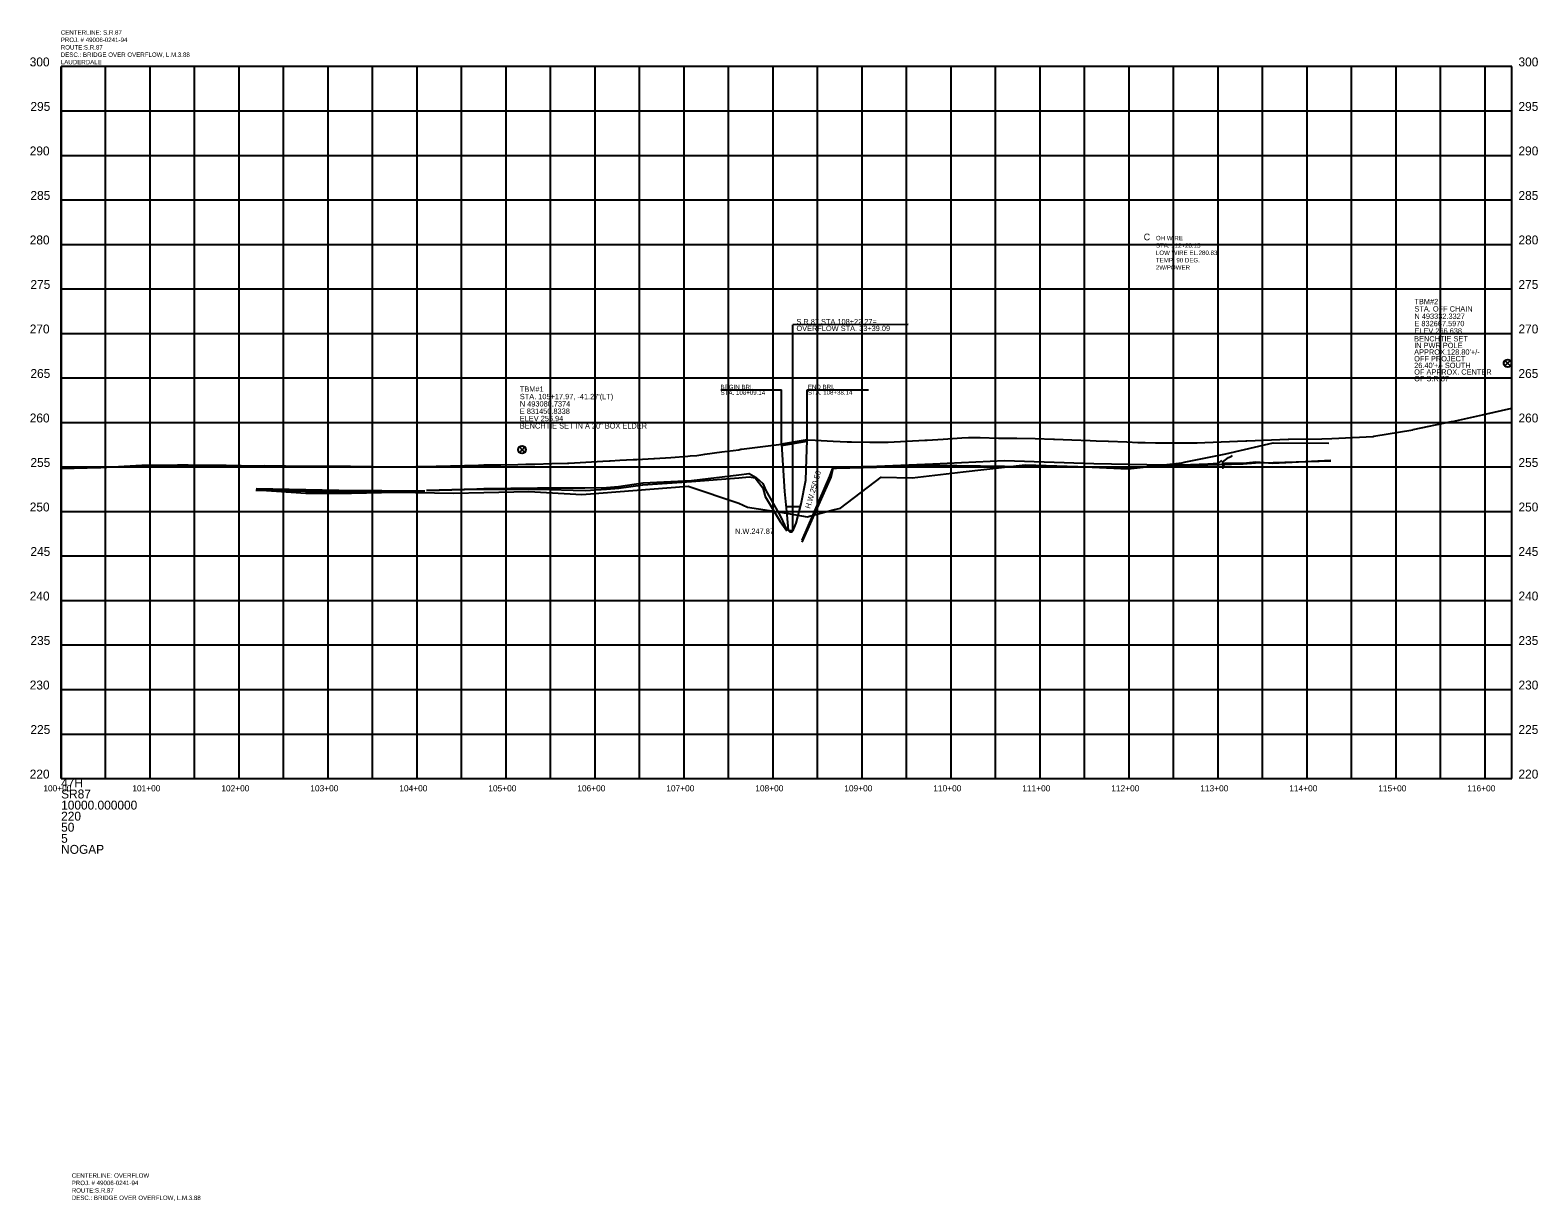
# Model space of a CAD drawing. Extents: x 818717 to 846077, y 440014 to 541392.
# Drawn here: x 836438 to 838132, y 493086 to 494401 of the extents above; entities that cross this region are included whole.
import ezdxf

# ---------------------------------------------------------------- set-up
doc = ezdxf.new("R2010")
doc.units = 0
for name, color, linetype in [('DESIGN - SHEET - Corner Text', 7, 'Continuous'), ('DESIGN - SHEET - Light Grid', 7, 'Continuous'), ('SURVEY - DRAINAGE - Bridge Hydraulic Data with Text', 7, 'Continuous'), ('SURVEY - PROFILE - Control with Text', 7, 'Continuous'), ('SURVEY - PROFILE - Drainage - Bridges', 7, 'Continuous'), ('SURVEY - PROFILE - Drainage - Bridges Text', 7, 'Continuous'), ('SURVEY - PROFILE - Drainage - Natural Features with Text', 7, 'Continuous'), ('SURVEY - PROFILE - Ground Line with Text', 7, 'Continuous'), ('SURVEY - PROFILE - Project Information and Notes', 7, 'Continuous'), ('SURVEY - PROFILE - Utilities - Overhead Wire Crossings', 7, 'Continuous'), ('SURVEY - PROFILE - Utilities - Telephone with Text', 7, 'Continuous'), ('SURVEY - PROFILE - Utilities - Water with Text', 7, 'Continuous')]:
    doc.layers.add(name, color=color, linetype=linetype)

msp = doc.modelspace()

# ---------------------------------------------------------------- linework, layer by layer
at = {"layer": 'DESIGN - SHEET - Light Grid'}
for p, q in [((838103.1, 494360.6), (836473.1, 494360.6)), ((836473.1, 494360.6), (836473.1, 493560.6)), ((836473.1, 493560.6), (836473.1, 494360.6)), ((836523.1, 493560.6), (836523.1, 494360.6)), ((836573.1, 493560.6), (836573.1, 494360.6)), ((836623.1, 493560.6), (836623.1, 494360.6)), ((836673.1, 493560.6), (836673.1, 494360.6)), ((836723.1, 493560.6), (836723.1, 494360.6)), ((836773.1, 493560.6), (836773.1, 494360.6)), ((836823.1, 493560.6), (836823.1, 494360.6)), ((836873.1, 493560.6), (836873.1, 494360.6)), ((836923.1, 493560.6), (836923.1, 494360.6)), ((836973.1, 493560.6), (836973.1, 494360.6)), ((837023.1, 493560.6), (837023.1, 494360.6)), ((837073.1, 493560.6), (837073.1, 494360.6)), ((837123.1, 493560.6), (837123.1, 494360.6)), ((837173.1, 493560.6), (837173.1, 494360.6)), ((837223.1, 493560.6), (837223.1, 494360.6)), ((837273.1, 493560.6), (837273.1, 494360.6)), ((837323.1, 493560.6), (837323.1, 494360.6)), ((837373.1, 493560.6), (837373.1, 494360.6)), ((837423.1, 493560.6), (837423.1, 494360.6)), ((837473.1, 493560.6), (837473.1, 494360.6)), ((837523.1, 493560.6), (837523.1, 494360.6)), ((837573.1, 493560.6), (837573.1, 494360.6)), ((837623.1, 493560.6), (837623.1, 494360.6)), ((837673.1, 493560.6), (837673.1, 494360.6)), ((837723.1, 493560.6), (837723.1, 494360.6)), ((837773.1, 493560.6), (837773.1, 494360.6)), ((837823.1, 493560.6), (837823.1, 494360.6)), ((837873.1, 493560.6), (837873.1, 494360.6)), ((837923.1, 493560.6), (837923.1, 494360.6)), ((837973.1, 493560.6), (837973.1, 494360.6)), ((838023.1, 493560.6), (838023.1, 494360.6)), ((838073.1, 493560.6), (838073.1, 494360.6)), ((838103.1, 493560.6), (838103.1, 494360.6)), ((836473.1, 494310.6), (838103.1, 494310.6)), ((836473.1, 494260.6), (838103.1, 494260.6)), ((836473.1, 494210.6), (838103.1, 494210.6)), ((836473.1, 494160.6), (838103.1, 494160.6)), ((836473.1, 494110.6), (838103.1, 494110.6)), ((836473.1, 494060.6), (838103.1, 494060.6)), ((836473.1, 494010.6), (838103.1, 494010.6)), ((836473.1, 493960.6), (838103.1, 493960.6)), ((836473.1, 493910.6), (838103.1, 493910.6)), ((836473.1, 493860.6), (838103.1, 493860.6)), ((836473.1, 493810.6), (838103.1, 493810.6)), ((836473.1, 493760.6), (838103.1, 493760.6)), ((836473.1, 493710.6), (838103.1, 493710.6)), ((836473.1, 493660.6), (838103.1, 493660.6)), ((836473.1, 493610.6), (838103.1, 493610.6)), ((836473.1, 493560.6), (838103.1, 493560.6)), ((836473.1, 493560.6), (838103.1, 493560.6)), ((836473.1, 493560.6), (836473.1, 493560.6))]:
    msp.add_line(p, q, dxfattribs=at)
at = {"layer": 'SURVEY - DRAINAGE - Bridge Hydraulic Data with Text'}
for p, q in [((837287.6, 493866.2), (837303.1, 493866.2)), ((837290.7, 493839.3), (837295, 493839.3))]:
    msp.add_line(p, q, dxfattribs=at)
at = {"layer": 'SURVEY - PROFILE - Control with Text'}
for p, q in [((838095.4, 494030.2), (838098.4, 494027.1)), ((838098.4, 494027.1), (838101.5, 494030.2)), ((838095.4, 494024.1), (838098.4, 494027.1)), ((838098.4, 494027.1), (838101.5, 494024.1)), ((836988, 493933.1), (836991, 493930)), ((836988, 493926.9), (836991, 493930)), ((836991, 493930), (836994.1, 493933.1)), ((836991, 493930), (836994.1, 493926.9))]:
    msp.add_line(p, q, dxfattribs=at)
for points in [[(838095.4, 494030.2), (838098.4, 494027.1), (838095.4, 494024.1), (838095.1, 494024.3), (838094.9, 494024.7), (838094.7, 494024.9), (838094.6, 494025.2), (838094.4, 494025.5), (838094.3, 494025.8), (838094.2, 494026.1), (838094.2, 494026.4), (838094.1, 494026.7), (838094.1, 494026.9), (838094.1, 494027.3), (838094.1, 494027.5), (838094.2, 494027.8), (838094.2, 494028), (838094.2, 494028.2), (838094.3, 494028.5), (838094.4, 494028.7), (838094.5, 494028.9), (838094.7, 494029.3), (838094.9, 494029.6), (838095.1, 494029.9)], [(838101.5, 494030.2), (838098.4, 494027.1), (838101.5, 494024.1), (838101.7, 494024.3), (838101.9, 494024.5), (838102.2, 494024.9), (838102.3, 494025.1), (838102.5, 494025.5), (838102.6, 494025.8), (838102.7, 494026.1), (838102.7, 494026.3), (838102.8, 494026.7), (838102.8, 494026.9), (838102.8, 494027.2), (838102.8, 494027.5), (838102.8, 494027.7), (838102.7, 494028), (838102.7, 494028.2), (838102.6, 494028.5), (838102.5, 494028.8), (838102.4, 494029), (838102.3, 494029.2), (838102, 494029.6), (838101.8, 494029.9)], [(836988, 493933.1), (836991, 493930), (836988, 493926.9), (836987.7, 493927.2), (836987.5, 493927.5), (836987.3, 493927.8), (836987.1, 493928.1), (836987, 493928.4), (836986.9, 493928.7), (836986.8, 493928.9), (836986.8, 493929.2), (836986.7, 493929.5), (836986.7, 493929.8), (836986.7, 493930.1), (836986.7, 493930.4), (836986.7, 493930.6), (836986.8, 493930.8), (836986.8, 493931), (836986.9, 493931.3), (836987, 493931.5), (836987.1, 493931.8), (836987.2, 493932.1), (836987.4, 493932.4), (836987.7, 493932.8)], [(836994.1, 493933.1), (836991, 493930), (836994.1, 493926.9), (836994.3, 493927.1), (836994.5, 493927.4), (836994.7, 493927.7), (836994.9, 493928), (836995.1, 493928.4), (836995.2, 493928.7), (836995.3, 493929), (836995.3, 493929.2), (836995.4, 493929.5), (836995.4, 493929.8), (836995.4, 493930.1), (836995.4, 493930.4), (836995.3, 493930.6), (836995.3, 493930.9), (836995.3, 493931.1), (836995.2, 493931.3), (836995, 493931.7), (836995, 493931.9), (836994.8, 493932.1), (836994.6, 493932.4), (836994.4, 493932.8)]]:
    msp.add_lwpolyline(points, close=True, dxfattribs=at)
for centre in [(838098.5, 494027.1), (836991, 493930)]:
    msp.add_circle(centre, 4.35, dxfattribs=at)
at = {"layer": 'SURVEY - PROFILE - Drainage - Bridges'}
for p, q in [((837311.2, 493941.1), (837282.5, 493936.3)), ((837311.2, 493939.2), (837282.6, 493934.5))]:
    msp.add_line(p, q, dxfattribs=at)
at = {"layer": 'SURVEY - PROFILE - Drainage - Bridges Text'}
for p, q in [((837214.2, 493997.4), (837282.5, 493997.4)), ((837311.2, 493997.4), (837380.1, 493997.4))]:
    msp.add_line(p, q, dxfattribs=at)
for points in [[(837282.5, 493936.3), (837282.5, 493997.4)], [(837311.2, 493941.1), (837311.2, 493997.4)]]:
    msp.add_lwpolyline(points, dxfattribs=at)
at = {"layer": 'SURVEY - PROFILE - Ground Line with Text'}
msp.add_line((837424.9, 494070.6), (837295.3, 494070.1), dxfattribs=at)
for points in [[(837295.3, 493839.9), (837295.3, 494070.1)], [(836473.1, 493908.8), (836473.6, 493908.8), (836516.6, 493909.9), (836517.7, 493909.9), (836563.6, 493912.5), (836564.6, 493912.6), (836603.9, 493912.8), (836616, 493912.8), (836658.4, 493912.6), (836692.2, 493912), (836701.8, 493912.3), (836702.1, 493912.3), (836748.6, 493911.4), (836749.4, 493911.4), (836797.7, 493911.5), (836798.4, 493911.5), (836847.2, 493910.7), (836847.9, 493910.7), (836848.3, 493910.7), (836894.4, 493911.5), (836895, 493911.5), (836941.9, 493912.7), (836948.2, 493912.8), (836967.3, 493913.1), (836986.4, 493913.4), (836995.1, 493913.6), (836995.7, 493913.6), (837005.5, 493913.8), (837024.6, 493914.3), (837042.1, 493914.7), (837043, 493914.7), (837043.7, 493914.8), (837062.8, 493915.9), (837081.9, 493917.1), (837089.4, 493917.6), (837089.7, 493917.6), (837090, 493917.6), (837101, 493918.2), (837115.9, 493918.9), (837120.1, 493919.1), (837139.2, 493920.1), (837139.5, 493920.1), (837139.9, 493920.1), (837158.3, 493921.4), (837177.4, 493922.8), (837179.9, 493923), (837187.3, 493923.5), (837196.5, 493924.8), (837215.6, 493927.4), (837234.7, 493930), (837237, 493930.4), (837237.5, 493930.4), (837282.5, 493936.3), (837286, 493883.2), (837288.5, 493856.9), (837290.1, 493839.5), (837291.7, 493837.7), (837294.3, 493837.7), (837296, 493840.2), (837298.9, 493847.5), (837304.6, 493869.3), (837309.9, 493895.9), (837310.6, 493919.3), (837311.2, 493940.5), (837311.2, 493941.1), (837320.2, 493940.6), (837340.6, 493939.5), (837356.3, 493938.7), (837361.2, 493938.7), (837381.8, 493938.5), (837401, 493938.4), (837401.4, 493938.4), (837402.5, 493938.5), (837423.1, 493939.5), (837443.7, 493940.6), (837445.8, 493940.8), (837446.3, 493940.8), (837464.3, 493941.9), (837485, 493943.2), (837492.5, 493943.7), (837493, 493943.7), (837493.5, 493943.7), (837505.6, 493943.5), (837526.2, 493943.1), (837540, 493942.9), (837540.9, 493942.9), (837541.5, 493942.9), (837546.8, 493942.8), (837567.4, 493942.4), (837588.3, 493941.9), (837589, 493941.9), (837589.4, 493941.9), (837608.7, 493941.1), (837629.3, 493940.4), (837636.2, 493940.1), (837649.5, 493939.6), (837649.9, 493939.6), (837670.5, 493938.7), (837683, 493938.2), (837688.7, 493938.1), (837691.2, 493938.1), (837702.9, 493937.8), (837703.3, 493937.8), (837711.8, 493937.8), (837732.4, 493937.7), (837736.2, 493937.7), (837749.6, 493937.6), (837758.3, 493938), (837804.2, 493939.9), (837804.6, 493940), (837805.2, 493940), (837852, 493941.8), (837852.5, 493941.8), (837889.6, 493942.3), (837900.7, 493942.4), (837947.4, 493944.9), (837948.2, 493945), (837991.9, 493952.4), (837992.4, 493952.5), (838035.2, 493961.6), (838036.3, 493961.8), (838070.1, 493969.1), (838071.7, 493969.4), (838103, 493976.5)]]:
    msp.add_lwpolyline(points, dxfattribs=at)
at = {"layer": 'SURVEY - PROFILE - Utilities - Telephone with Text'}
for points in [[(837305.6, 493828.4), (837337, 493900.3), (837340.6, 493910.5), (837344, 493910.5), (837389.5, 493911.4), (837452.7, 493914), (837533, 493917.7), (837633.4, 493914.4), (837693, 493913.5), (837732.4, 493913.1), (837761.4, 493912.8), (837801.2, 493914.1), (837815.3, 493915.2), (837834.8, 493915.6), (837899.7, 493917.6)], [(837305.7, 493826.2), (837338.5, 493899.1), (837340.6, 493909.1), (837344.3, 493909.1), (837389.4, 493910.3), (837452.7, 493912.5), (837533.1, 493911.4), (837634, 493910.4), (837693, 493911.1), (837732.4, 493912.9), (837761.4, 493914.2), (837773.6, 493914.7), (837777.1, 493918.4)], [(837777.9, 493916.4), (837778.4, 493909.3), (837780.8, 493914.9), (837801.2, 493914.8), (837815.6, 493916.3), (837834.7, 493914.8), (837899.6, 493918.4)], [(837778.2, 493916.1), (837784.7, 493921.3), (837787.8, 493922.4), (837789.4, 493923.4)], [(836883.8, 493884.4), (836940.3, 493886.2), (836948.2, 493886.3), (837008.5, 493887.2), (837061.7, 493887.1), (837085.9, 493887.4), (837099.3, 493888.5), (837126.9, 493892.6), (837181.4, 493895.4), (837234.7, 493901.9), (837246.2, 493903.4), (837253.9, 493898.8), (837261.4, 493892.1), (837265, 493884.3), (837281.2, 493855.7), (837288.6, 493839.7)], [(836884.1, 493884), (836940.5, 493885.5), (836948.2, 493885.5), (837008.3, 493885.5), (837061.9, 493884.1), (837085.8, 493885.6), (837099.6, 493886.9), (837126.6, 493890.5), (837181.5, 493894.1), (837234.7, 493898.5), (837246.3, 493899.5), (837253, 493898.5), (837261.5, 493887.2), (837264.1, 493877.3), (837281, 493849.3), (837288.6, 493838.7)], [(836692, 493884.7), (836784.9, 493882.7), (836881.4, 493882.5)], [(836692.2, 493886.5), (836785.1, 493884.6), (836881.6, 493883.8)]]:
    msp.add_lwpolyline(points, dxfattribs=at)
at = {"layer": 'SURVEY - PROFILE - Utilities - Water with Text'}
msp.add_lwpolyline([(836693.1, 493885), (836748.2, 493881.3), (836799.4, 493881.1), (836849.8, 493882.1), (836913.9, 493881.3), (836948.2, 493882), (836998.6, 493883.2), (837058.3, 493879.7), (837177.7, 493888.9), (837234.7, 493870), (837244.4, 493865.6), (837281.3, 493859.8), (837311.4, 493854.5), (837340.6, 493862.4), (837348.9, 493864.4), (837394.4, 493899.2), (837429.5, 493898.4), (837486.8, 493905.2), (837556.3, 493913), (837615.6, 493911.2), (837672, 493908.4), (837732.4, 493915.3), (837735.1, 493916.1), (837781.9, 493925.5), (837834.9, 493937.6), (837897.6, 493937.4)], dxfattribs=at)

# ---------------------------------------------------------------- texts
at = {"layer": 'DESIGN - SHEET - Corner Text'}
for s, height, p in [('300', 10, (836437.8, 494360.6)), ('300', 10, (838110.6, 494360.6)), ('295', 10, (836438.6, 494310.6)), ('295', 10, (838110.6, 494310.6)), ('290', 10, (836437.8, 494260.6)), ('290', 10, (838110.6, 494260.6)), ('285', 10, (836438.6, 494210.6)), ('285', 10, (838110.6, 494210.6)), ('280', 10, (836437.8, 494160.6)), ('280', 10, (838110.6, 494160.6)), ('275', 10, (836438.6, 494110.6)), ('275', 10, (838110.6, 494110.6)), ('270', 10, (836437.8, 494060.6)), ('270', 10, (838110.6, 494060.6)), ('265', 10, (836438.6, 494010.6)), ('265', 10, (838110.6, 494010.6)), ('260', 10, (836437.8, 493960.6)), ('260', 10, (838110.6, 493960.6)), ('255', 10, (836438.6, 493910.6)), ('255', 10, (838110.6, 493910.6)), ('250', 10, (836437.8, 493860.6)), ('250', 10, (838110.6, 493860.6)), ('245', 10, (836438.6, 493810.6)), ('245', 10, (838110.6, 493810.6)), ('240', 10, (836437.8, 493760.6)), ('240', 10, (838110.6, 493760.6)), ('235', 10, (836438.6, 493710.6)), ('235', 10, (838110.6, 493710.6)), ('230', 10, (836437.8, 493660.6)), ('230', 10, (838110.6, 493660.6)), ('225', 10, (836438.6, 493610.6)), ('225', 10, (838110.6, 493610.6)), ('220', 10, (836437.8, 493560.6)), ('220', 10, (838110.6, 493560.6)), ('100+00', 7, (836453.1, 493546.1)), ('101+00', 7, (836553.1, 493546.1)), ('102+00', 7, (836653.1, 493546.1)), ('103+00', 7, (836753.1, 493546.1)), ('104+00', 7, (836853.1, 493546.1)), ('105+00', 7, (836953.1, 493546.1)), ('106+00', 7, (837053.1, 493546.1)), ('107+00', 7, (837153.1, 493546.1)), ('108+00', 7, (837253.1, 493546.1)), ('109+00', 7, (837353.1, 493546.1)), ('110+00', 7, (837453.1, 493546.1)), ('111+00', 7, (837553.1, 493546.1)), ('112+00', 7, (837653.1, 493546.1)), ('113+00', 7, (837753.1, 493546.1)), ('114+00', 7, (837853.1, 493546.1)), ('115+00', 7, (837953.1, 493546.1)), ('116+00', 7, (838053.1, 493546.1))]:
    msp.add_text(s, height=height, dxfattribs=at).set_placement(p)
at = {"layer": 'DESIGN - SHEET - Light Grid'}
for s, p in [('47H', (836473.1, 493550.6)), ('SR87', (836473.1, 493538.2)), ('220', (836473.1, 493513.3)), ('10000.000000', (836473.1, 493525.7)), ('50', (836473.1, 493500.9)), ('5', (836473.1, 493488.4)), ('NOGAP', (836473.1, 493476))]:
    msp.add_text(s, height=10, dxfattribs=at).set_placement(p)
at = {"layer": 'SURVEY - PROFILE - Control with Text'}
for s, p in [('TBM#2', (837993.7, 494093.4)), ('STA. OFF CHAIN', (837993.7, 494085.2)), ('N 493332.3327', (837993.7, 494076.9)), ('E 832667.5970', (837993.7, 494068.7)), ('ELEV 266.638', (837993.7, 494060.4)), ('BENCHTIE SET ', (837993.4, 494051.6)), ('IN PWR POLE', (837993.4, 494044.1)), ("APPROX.128.80'+/-", (837993.4, 494036.7)), ('OFF PROJECT', (837993.4, 494029.2)), ("26.40'+/- SOUTH", (837993.4, 494021.7)), ('OF APPROX. CENTER', (837993.4, 494014.3)), ('OF S.R.87', (837993.4, 494006.8)), ('TBM#1', (836988.5, 493995)), ("STA. 105+17.97, -41.27'(LT)", (836988.5, 493986.7)), ('N 493080.7374', (836988.5, 493978.5)), ('E 831450.8338', (836988.5, 493970.2)), ('ELEV 256.94', (836988.5, 493962)), ('BENCHTIE SET IN A 20" BOX ELDER', (836988.5, 493953.7))]:
    msp.add_text(s, height=6, dxfattribs=at).set_placement(p)
at = {"layer": 'SURVEY - PROFILE - Drainage - Bridges Text'}
for s, p in [('STA. 108+09.14', (837214.1, 493991.6)), ('BEGIN BRI.', (837214.1, 493997.9)), ('STA. 108+38.14', (837312.1, 493991.8)), ('END BRI.', (837312.1, 493998))]:
    msp.add_text(s, height=5, dxfattribs=at).set_placement(p)
at = {"layer": 'SURVEY - PROFILE - Drainage - Natural Features with Text'}
msp.add_text('H.W.250.56', height=6, rotation=73.3748, dxfattribs=at).set_placement((837314.6, 493863.3))
msp.add_text('N.W.247.87', height=6, dxfattribs=at).set_placement((837230.3, 493835.4))
at = {"layer": 'SURVEY - PROFILE - Ground Line with Text'}
for s, p in [('S.R.87 STA.108+22.27=', (837299.3, 494070.8)), ('OVERFLOW STA. 33+39.09', (837299.3, 494063.3))]:
    msp.add_text(s, height=6, dxfattribs=at).set_placement(p)
at = {"layer": 'SURVEY - PROFILE - Project Information and Notes'}
for s, height, p in [('CENTERLINE: S.R.87', 4.998, (836472.7, 494396.2)), ('PROJ. # 49006-0241-94', 4.998, (836472.7, 494387.9)), ('ROUTE:S.R.87', 4.998, (836472.7, 494379.5)), ('DESC.: BRIDGE OVER OVERFLOW, L.M.3.88', 4.998, (836472.7, 494371.2)), ('LAUDERDALE', 5, (836472.7, 494362.9)), ('CENTERLINE: OVERFLOW', 4.998, (836485, 493112.1)), ('PROJ. # 49006-0241-94', 4.998, (836485, 493103.8)), ('ROUTE:S.R.87', 4.998, (836485, 493095.4)), ('DESC.: BRIDGE OVER OVERFLOW, L.M.3.88', 4.998, (836485, 493087.1))]:
    msp.add_text(s, height=height, dxfattribs=at).set_placement(p)
at = {"layer": 'SURVEY - PROFILE - Utilities - Overhead Wire Crossings'}
for s, height, p in [('C', 7.5, (837689.5, 494165.2)), ('OH WIRE', 5, (837703.2, 494165.2)), ('STA. 112+20.15', 5, (837703.2, 494156.9)), ("LOW WIRE EL.280.83'", 5, (837703.2, 494148.7)), ('TEMP. 90 DEG.', 5, (837703.2, 494140.4)), ('2W/POWER', 5, (837703.2, 494132.2))]:
    msp.add_text(s, height=height, dxfattribs=at).set_placement(p)

doc.saveas('drawing.dxf')
